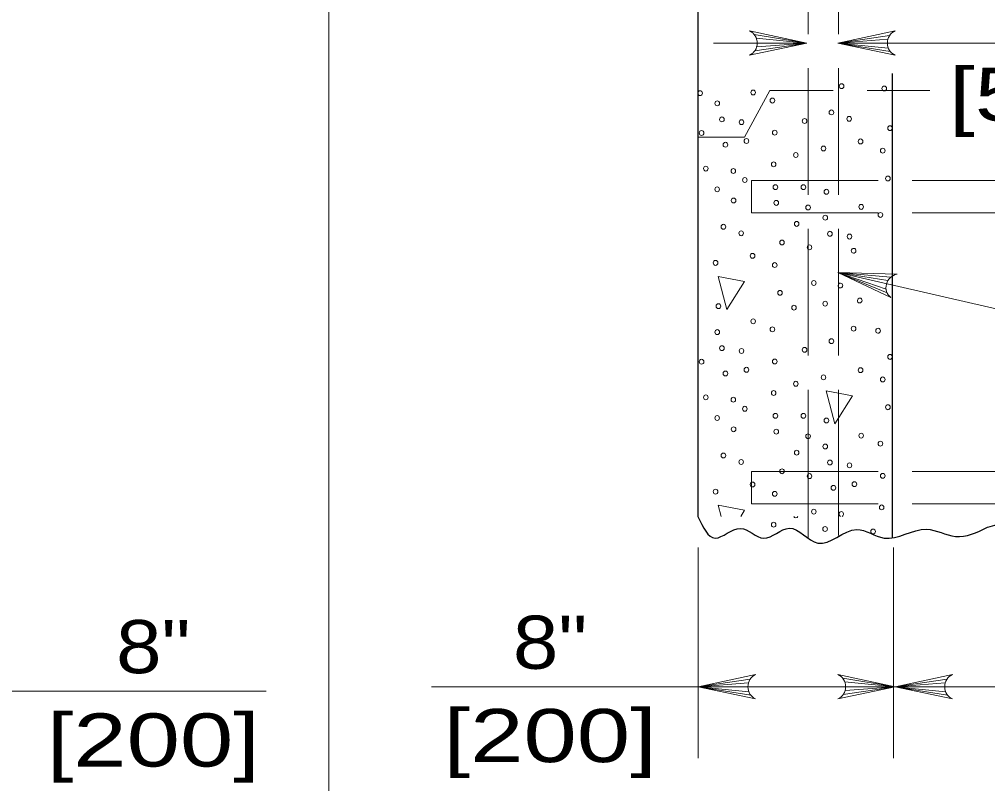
# Model space of a CAD drawing. Extents: x 1329.9 to 1363.9, y 715.5 to 737.5.
# Drawn here: x 1338.52 to 1341.364, y 728.685 to 730.929 of the extents above; entities that cross this region are included whole.
import ezdxf
from ezdxf.enums import TextEntityAlignment as Align

# ---------------------------------------------------------------- set-up
doc = ezdxf.new("R2010")
doc.units = 0
doc.header["$LTSCALE"] = 0.062
doc.linetypes.add('LONG_DASHED', pattern=[7.5, 6, -1.5])
doc.linetypes.add('MEDIUM_DASHED', pattern=[4.5, 3, -1.5])
doc.layers.add('1', color=7, linetype='Continuous', lineweight=13)

msp = doc.modelspace()

# ---------------------------------------------------------------- linework, layer by layer
at = {"layer": '1', "lineweight": 25}
for p, q in [((1340.51358, 732.78242), (1340.51358, 729.46942)), ((1341.08508, 730.099), (1341.08508, 730.76967)), ((1341.08508, 729.46942), (1341.08508, 730.099)), ((1341.08508, 729.40883), (1341.08508, 729.46942))]:
    msp.add_line(p, q, dxfattribs=at)
at = {"layer": '1'}
for p, q in [((1340.679, 730.88417), (1340.83308, 730.85925)), ((1340.68483, 730.87375), (1340.83308, 730.85925)), ((1341.0765, 730.88183), (1340.92425, 730.85925)), ((1341.07133, 730.87067), (1340.92425, 730.85925)), ((1340.5595, 730.85925), (1340.83308, 730.85925)), ((1340.68083, 730.83667), (1340.83308, 730.85925)), ((1340.686, 730.84783), (1340.83308, 730.85925)), ((1340.6875, 730.85925), (1340.83308, 730.85925)), ((1341.06983, 730.85925), (1340.92425, 730.85925)), ((1341.0725, 730.84475), (1340.92425, 730.85925)), ((1341.07833, 730.83433), (1340.92425, 730.85925)), ((1340.92425, 730.85925), (1341.76567, 730.85925)), ((1341.79758, 729.9845), (1340.92467, 730.18533)), ((1341.06592, 730.137), (1340.92467, 730.18533)), ((1341.06892, 730.12567), (1340.92467, 730.18533)), ((1341.07158, 730.16217), (1340.92467, 730.18533)), ((1341.0795, 730.17175), (1340.92467, 730.18533)), ((1340.65067, 729.48742), (1340.57275, 729.50258)), ((1340.57275, 729.50258), (1340.5815, 729.46942)), ((1340.63925, 729.46942), (1340.65067, 729.48742)), ((1340.5145, 729.37808), (1340.5145, 729.3015)), ((1340.5145, 729.36483), (1340.5145, 728.75908)), ((1341.08742, 729.378), (1341.08742, 729.3015)), ((1341.08742, 729.36483), (1341.08742, 728.75908)), ((1340.66683, 728.99167), (1340.5145, 728.96908)), ((1340.93875, 728.99408), (1341.09283, 728.96908)), ((1341.24508, 728.99167), (1341.09283, 728.96908)), ((1340.94725, 728.96908), (1339.73108, 728.96908)), ((1340.66167, 728.9805), (1340.5145, 728.96908)), ((1340.66008, 728.96908), (1340.5145, 728.96908)), ((1340.66275, 728.95467), (1340.5145, 728.96908)), ((1340.66858, 728.94417), (1340.5145, 728.96908)), ((1341.09283, 728.96908), (1340.88108, 728.96908)), ((1340.9405, 728.94658), (1341.09283, 728.96908)), ((1340.94458, 728.98358), (1341.09283, 728.96908)), ((1340.94567, 728.95775), (1341.09283, 728.96908)), ((1340.94725, 728.96908), (1341.09283, 728.96908)), ((1341.24, 728.9805), (1341.09283, 728.96908)), ((1341.23842, 728.96908), (1341.09283, 728.96908)), ((1341.24108, 728.95467), (1341.09283, 728.96908)), ((1341.24692, 728.94417), (1341.09283, 728.96908)), ((1339.24542, 728.95625), (1337.8955, 728.95625))]:
    msp.add_line(p, q, dxfattribs=at)
at = {"layer": '1', "linetype": 'MEDIUM_DASHED'}
for p, q in [((1340.72483, 730.71958), (1340.6505, 730.58333)), ((1340.72483, 730.71958), (1341.19417, 730.71958)), ((1340.51592, 730.58333), (1340.6505, 730.58333))]:
    msp.add_line(p, q, dxfattribs=at)
at = {"layer": '1', "linetype": 'LONG_DASHED'}
for p, q in [((1340.67083, 730.45583), (1345.98667, 730.45583)), ((1340.67083, 730.45583), (1340.67083, 730.36083)), ((1340.67083, 730.36083), (1345.98667, 730.36083)), ((1340.67083, 729.60092), (1345.98667, 729.60092)), ((1340.67083, 729.60092), (1340.67083, 729.50592)), ((1340.67083, 729.50592), (1345.98667, 729.50592))]:
    msp.add_line(p, q, dxfattribs=at)
for points in [[(1340.83683, 729.40367), (1340.83683, 729.46942), (1340.83683, 733.37567)], [(1340.92608, 729.41367), (1340.92608, 729.46942), (1340.92608, 733.37567)]]:
    msp.add_lwpolyline(points, dxfattribs=at)
at = {"layer": '1'}
for points in [[(1339.42875, 725.87033), (1339.42875, 729.46942), (1339.42875, 732.83242)], [(1340.66492, 730.89492), (1340.83308, 730.85925), (1340.66492, 730.82367)], [(1341.09242, 730.82367), (1340.92425, 730.85925), (1341.09242, 730.89492)], [(1341.07992, 730.11208), (1340.92467, 730.18533), (1341.0985, 730.18058)], [(1340.68275, 728.9335), (1340.5145, 728.96908), (1340.68275, 729.00475)], [(1340.92458, 729.00475), (1341.09283, 728.96908), (1340.92458, 728.9335)], [(1341.26108, 728.9335), (1341.09283, 728.96908), (1341.26108, 729.00475)], [(1345.54308, 728.96908), (1344.87642, 728.96908), (1341.09283, 728.96908)]]:
    msp.add_lwpolyline(points, dxfattribs=at)
for points in [[(1340.57275, 730.17425), (1340.59842, 730.07692), (1340.65067, 730.15908)], [(1340.89, 729.83842), (1340.91567, 729.74108), (1340.96783, 729.82317)]]:
    msp.add_lwpolyline(points, close=True, dxfattribs=at)
for centre, major_axis, start_param, end_param in [((1340.65123, 730.85925), (0, -0.03844), 0.3855052, 2.7561184), ((1341.10611, 730.85926), (0, 0.03844), 0.3855052, 2.7561184), ((1341.10258, 730.14319), (0.01996, 0.03285), 0.6825652, 3.0531783), ((1340.9346, 729.47621), (0, 0.00718), 3.4875052, 9.0788653), ((1340.8009, 729.47219), (0, 0.00718), 1.9609233, 4.322262), ((1340.6964, 728.96912), (0, 0.03844), 0.3855052, 2.7561184), ((1340.91095, 728.96911), (0, -0.03844), 0.3855052, 2.7561184), ((1341.2747, 728.96911), (0, 0.03844), 0.3855052, 2.7561184)]:
    msp.add_ellipse(centre, major_axis=major_axis, ratio=0.944544, start_param=start_param, end_param=end_param, dxfattribs=at)
for centre, major_axis in [((1340.93545, 730.73275), (0, 0.00718)), ((1341.06074, 730.72581), (0, 0.00718)), ((1340.51976, 730.71221), (0, 0.00718)), ((1340.67561, 730.714), (0, 0.00718)), ((1340.73212, 730.69043), (0, 0.00718)), ((1340.57025, 730.68226), (0, 0.00718)), ((1340.58399, 730.63514), (0, 0.00718)), ((1340.82665, 730.63032), (0, 0.00718)), ((1340.90547, 730.65568), (0, 0.00718)), ((1340.95771, 730.63665), (0, 0.00718)), ((1340.64135, 730.62691), (0, 0.00718)), ((1341.07761, 730.60945), (0, 0.00718)), ((1340.52399, 730.59523), (0, 0.00718)), ((1340.739, 730.59607), (0, 0.00718)), ((1340.5942, 730.56075), (0, 0.00718)), ((1340.65589, 730.57167), (0, 0.00718)), ((1340.88232, 730.54956), (0, 0.00718)), ((1340.99107, 730.57043), (0, 0.00718)), ((1340.8009, 730.53053), (0, 0.00718)), ((1341.0562, 730.54323), (0, 0.00718)), ((1340.53657, 730.49068), (0, 0.00718)), ((1340.73588, 730.50333), (0, 0.00718)), ((1340.6174, 730.48368), (0, 0.00718)), ((1341.07163, 730.46163), (0, 0.00718)), ((1340.56998, 730.42989), (0, 0.00718)), ((1340.65108, 730.45709), (0, 0.00718)), ((1340.74101, 730.43622), (0, 0.00718)), ((1340.82327, 730.43622), (0, 0.00718)), ((1340.89088, 730.42262), (0, 0.00718)), ((1340.61825, 730.39693), (0, 0.00718)), ((1340.74354, 730.38998), (0, 0.00718)), ((1340.83696, 730.37638), (0, 0.00718)), ((1340.99281, 730.37818), (0, 0.00718)), ((1340.88745, 730.34644), (0, 0.00718)), ((1341.04932, 730.35461), (0, 0.00718)), ((1340.58828, 730.31985), (0, 0.00718)), ((1340.80349, 730.32831), (0, 0.00718)), ((1340.64051, 730.30082), (0, 0.00718)), ((1340.90119, 730.29931), (0, 0.00718)), ((1340.95855, 730.29109), (0, 0.00718)), ((1340.76041, 730.27362), (0, 0.00718)), ((1340.84119, 730.25941), (0, 0.00718)), ((1340.67387, 730.23461), (0, 0.00718)), ((1340.97082, 730.24933), (0.00328, 0.00639)), ((1340.56512, 730.21373), (0, 0.00718)), ((1340.739, 730.20741), (0, 0.00718)), ((1340.85377, 730.15485), (0, 0.00718)), ((1340.93189, 730.14724), (0.00051, 0.00716)), ((1340.75443, 730.1258), (0, 0.00718)), ((1340.88718, 730.09407), (0, 0.00718)), ((1340.98872, 730.10336), (0.00328, 0.00639)), ((1340.57368, 730.08679), (0, 0.00718)), ((1340.79556, 730.08226), (0, 0.00718)), ((1340.67561, 730.04235), (0, 0.00718)), ((1340.57025, 730.01062), (0, 0.00718)), ((1340.73212, 730.01879), (0, 0.00718)), ((1340.97061, 730.02063), (0, 0.00718)), ((1341.04242, 730.01457), (0.00328, 0.00639)), ((1340.90547, 729.98403), (0, 0.00718)), ((1340.58399, 729.96349), (0, 0.00718)), ((1340.64135, 729.95526), (0, 0.00718)), ((1340.82665, 729.95868), (0, 0.00718)), ((1340.52399, 729.92358), (0, 0.00718)), ((1340.739, 729.92442), (0, 0.00718)), ((1341.07761, 729.9378), (0, 0.00718)), ((1340.65589, 729.90002), (0, 0.00718)), ((1340.99107, 729.89879), (0, 0.00718)), ((1340.5942, 729.88911), (0, 0.00718)), ((1340.88232, 729.87791), (0, 0.00718)), ((1341.0562, 729.87159), (0, 0.00718)), ((1340.8009, 729.85888), (0, 0.00718)), ((1340.53657, 729.81903), (0, 0.00718)), ((1340.6174, 729.81203), (0, 0.00718)), ((1340.73588, 729.83168), (0, 0.00718)), ((1340.65108, 729.78545), (0, 0.00718)), ((1341.07163, 729.78998), (0, 0.00718)), ((1340.56998, 729.75825), (0, 0.00718)), ((1340.74101, 729.76457), (0, 0.00718)), ((1340.82327, 729.76457), (0, 0.00718)), ((1340.89088, 729.75097), (0, 0.00718)), ((1340.61825, 729.72528), (0, 0.00718)), ((1340.74354, 729.71834), (0, 0.00718)), ((1340.83696, 729.70474), (0, 0.00718)), ((1340.99281, 729.70653), (0, 0.00718)), ((1340.88745, 729.67479), (0, 0.00718)), ((1341.04932, 729.68297), (0, 0.00718)), ((1340.58828, 729.64821), (0, 0.00718)), ((1340.80349, 729.65666), (0, 0.00718)), ((1340.64051, 729.62918), (0, 0.00718)), ((1340.90119, 729.62767), (0, 0.00718)), ((1340.95855, 729.61944), (0, 0.00718)), ((1340.76041, 729.60198), (0, 0.00718)), ((1340.84119, 729.58776), (0, 0.00718)), ((1341.0562, 729.5886), (0, 0.00718)), ((1340.67387, 729.56297), (0, 0.00718)), ((1340.9114, 729.55328), (0, 0.00718)), ((1340.97309, 729.5642), (0, 0.00718)), ((1340.56512, 729.54209), (0, 0.00718)), ((1340.739, 729.53576), (0, 0.00718)), ((1341.05308, 729.49586), (0, 0.00718)), ((1340.85377, 729.48321), (0, 0.00718)), ((1340.73588, 729.44498), (0, 0.00718)), ((1340.88678, 729.43233), (0, 0.00718)), ((1341.02792, 729.42518), (0, 0.00718))]:
    msp.add_ellipse(centre, major_axis=major_axis, ratio=0.944544, dxfattribs=at)
at = {"layer": '1', "lineweight": 25}
for points in [[(1340.51358, 729.46942), (1340.56425, 729.40558), (1340.63792, 729.43417), (1340.70683, 729.40525), (1340.78142, 729.43483), (1340.86525, 729.39133), (1340.97992, 729.43083), (1341.06, 729.40583), (1341.18492, 729.43175), (1341.26975, 729.41075), (1341.36442, 729.43742)], [(1341.36442, 729.43742), (1341.39275, 729.44542), (1341.51858, 729.41275), (1341.65275, 729.43875), (1341.7655, 729.3935), (1341.92017, 729.438), (1342.03292, 729.39758), (1342.14758, 729.44683), (1342.26033, 729.40833), (1342.362, 729.43617), (1342.47467, 729.4045), (1342.58558, 729.42642), (1342.69275, 729.39958), (1342.8055, 729.44692), (1342.95367, 729.40475), (1343.08133, 729.43842), (1343.18292, 729.40375), (1343.37025, 729.43092), (1343.50908, 729.41792), (1343.60792, 729.43683), (1343.71875, 729.39742), (1343.83525, 729.436), (1343.96475, 729.3985), (1344.14842, 729.42075), (1344.26117, 729.40175), (1344.41208, 729.42783), (1344.50058, 729.38433), (1344.65067, 729.42892), (1344.78017, 729.38567), (1344.99492, 729.41017)]]:
    msp.add_spline(points, degree=3, dxfattribs=at)

# ---------------------------------------------------------------- texts
at = {"layer": '1'}
for s, width, p in [('[50]', 1.3, (1341.47771, 730.63092)), ('8"', 1.15, (1338.9135, 729.009)), ('8"', 1.15, (1340.07917, 729.022)), ('[200]', 1.35, (1340.07917, 728.74792)), ('[200]', 1.35, (1338.9135, 728.73492))]:
    msp.add_text(s, height=0.156, dxfattribs=dict(at, width=width)).set_placement(p, align=Align.CENTER)

doc.saveas('drawing.dxf')
